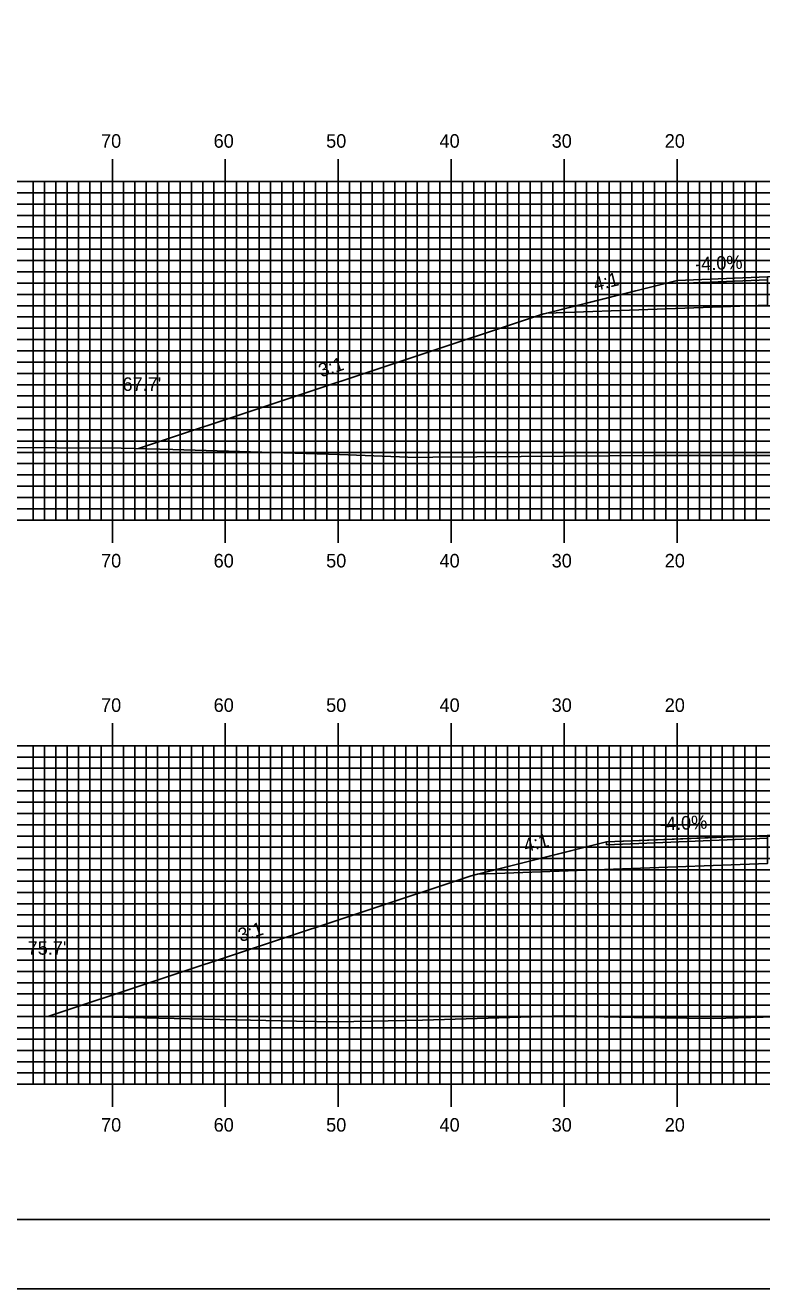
# Model space of a CAD drawing. Extents: x 1762578 to 1762921, y 442591 to 442811.
# Drawn here: x 1762666.1 to 1762731.3, y 442590.5 to 442702.5 of the extents above; entities that cross this region are included whole.
import ezdxf

# ---------------------------------------------------------------- set-up
doc = ezdxf.new("R2010")
doc.units = 0
for name, color, linetype in [('ANNOTATION', 7, 'Continuous'), ('BORDER', 7, 'Continuous'), ('D_Roadway_Centerline', 7, 'Continuous'), ('D_Roadway_Edge_Shoulder', 7, 'Continuous'), ('D_Roadway_SlopeLines', 7, 'Continuous'), ('D_Roadway_SubGrade', 7, 'Continuous'), ('D_Text_Standard', 7, 'Continuous'), ('H_V ANNOTATION', 7, 'Continuous'), ('MAJOR', 7, 'Continuous'), ('MINOR', 7, 'Continuous'), ('PLOT BOUNDARY', 7, 'Continuous'), ('S_Roadway_Centerline', 7, 'Continuous')]:
    doc.layers.add(name, color=color, linetype=linetype)

msp = doc.modelspace()

# ---------------------------------------------------------------- linework, layer by layer
at = {"layer": 'BORDER'}
msp.add_lwpolyline([(1762594.18, 442596.67), (1762914.18, 442596.67), (1762914.18, 442806.67), (1762594.18, 442806.67)], close=True, dxfattribs=at)
at = {"layer": 'D_Roadway_Centerline'}
for points in [[(1762676.09, 442665.01), (1762676.09, 442665.01), (1762711.78, 442676.9), (1762712, 442676.96), (1762712.25, 442677.02), (1762712.25, 442677.02), (1762716.68, 442678.13), (1762723.78, 442679.9), (1762723.78, 442679.9), (1762731.78, 442680.22), (1762739.05, 442680.48), (1762743.78, 442680.66), (1762743.78, 442680.66), (1762755.78, 442681.09), (1762763.78, 442680.77), (1762764.26, 442680.65), (1762773.95, 442678.22), (1762775.78, 442677.77), (1762805.93, 442667.72), (1762805.95, 442667.71)], [(1762668.07, 442614.67), (1762668.08, 442614.67), (1762705.54, 442627.15), (1762706.12, 442627.3), (1762706.12, 442627.3), (1762717.54, 442630.15), (1762717.54, 442630.15), (1762726.98, 442630.53), (1762731.78, 442630.72), (1762731.78, 442630.72), (1762738.78, 442630.98), (1762743.78, 442631.16), (1762743.78, 442631.16), (1762750.76, 442631.41), (1762755.78, 442631.59), (1762755.78, 442631.59), (1762763.78, 442631.27), (1762773.95, 442628.72), (1762773.95, 442628.72), (1762774.91, 442628.48), (1762775.78, 442628.27), (1762802.49, 442619.36), (1762811.53, 442616.35)]]:
    msp.add_lwpolyline(points, dxfattribs=at)
at = {"layer": 'D_Roadway_Edge_Shoulder'}
for points in [[(1762731.78, 442680.22), (1762723.78, 442679.9), (1762723.78, 442679.65), (1762731.78, 442679.97)], [(1762731.78, 442630.72), (1762717.54, 442630.15), (1762717.54, 442629.9), (1762731.78, 442630.47)]]:
    msp.add_lwpolyline(points, close=True, dxfattribs=at)
at = {"layer": 'D_Roadway_SlopeLines'}
for points in [[(1762723.78, 442679.9), (1762711.78, 442676.9), (1762676.09, 442665.01)], [(1762717.54, 442630.15), (1762705.54, 442627.15), (1762668.07, 442614.67)]]:
    msp.add_lwpolyline(points, dxfattribs=at)
at = {"layer": 'D_Roadway_SubGrade'}
for points in [[(1762723.78, 442679.65), (1762731.78, 442679.97), (1762731.78, 442679.56), (1762731.78, 442677.72), (1762712.25, 442677.02), (1762723.78, 442679.9)], [(1762717.54, 442629.9), (1762731.78, 442630.47), (1762731.78, 442630.06), (1762731.78, 442628.22), (1762706.12, 442627.3), (1762717.54, 442630.15)]]:
    msp.add_lwpolyline(points, close=True, dxfattribs=at)
at = {"layer": 'MAJOR'}
for p, q in [((1762673.78, 442690.67), (1762673.78, 442688.67)), ((1762683.78, 442690.67), (1762683.78, 442688.67)), ((1762693.78, 442690.67), (1762693.78, 442688.67)), ((1762703.78, 442690.67), (1762703.78, 442688.67)), ((1762713.78, 442690.67), (1762713.78, 442688.67)), ((1762723.78, 442690.67), (1762723.78, 442688.67)), ((1762603.78, 442688.67), (1762883.78, 442688.67)), ((1762603.78, 442688.67), (1762883.78, 442688.67)), ((1762673.78, 442658.67), (1762673.78, 442688.67)), ((1762683.78, 442658.67), (1762683.78, 442688.67)), ((1762693.78, 442658.67), (1762693.78, 442688.67)), ((1762703.78, 442658.67), (1762703.78, 442688.67)), ((1762713.78, 442658.67), (1762713.78, 442688.67)), ((1762723.78, 442658.67), (1762723.78, 442688.67)), ((1762603.78, 442683.67), (1762883.78, 442683.67)), ((1762603.78, 442678.67), (1762883.78, 442678.67)), ((1762603.78, 442673.67), (1762883.78, 442673.67)), ((1762603.78, 442668.67), (1762883.78, 442668.67)), ((1762603.78, 442663.67), (1762883.78, 442663.67)), ((1762603.78, 442658.67), (1762883.78, 442658.67)), ((1762603.78, 442658.67), (1762883.78, 442658.67)), ((1762673.78, 442656.66), (1762673.78, 442658.67)), ((1762683.78, 442656.66), (1762683.78, 442658.67)), ((1762693.78, 442656.66), (1762693.78, 442658.67)), ((1762703.78, 442656.66), (1762703.78, 442658.67)), ((1762713.78, 442656.66), (1762713.78, 442658.67)), ((1762723.78, 442656.66), (1762723.78, 442658.67)), ((1762673.78, 442640.67), (1762673.78, 442638.67)), ((1762683.78, 442640.67), (1762683.78, 442638.67)), ((1762693.78, 442640.67), (1762693.78, 442638.67)), ((1762703.78, 442640.67), (1762703.78, 442638.67)), ((1762713.78, 442640.67), (1762713.78, 442638.67)), ((1762723.78, 442640.67), (1762723.78, 442638.67)), ((1762603.78, 442638.67), (1762883.78, 442638.67)), ((1762603.78, 442638.67), (1762883.78, 442638.67)), ((1762673.78, 442608.67), (1762673.78, 442638.67)), ((1762683.78, 442608.67), (1762683.78, 442638.67)), ((1762693.78, 442608.67), (1762693.78, 442638.67)), ((1762703.78, 442608.67), (1762703.78, 442638.67)), ((1762713.78, 442608.67), (1762713.78, 442638.67)), ((1762723.78, 442608.67), (1762723.78, 442638.67)), ((1762603.78, 442633.67), (1762883.78, 442633.67)), ((1762603.78, 442628.67), (1762883.78, 442628.67)), ((1762603.78, 442623.67), (1762883.78, 442623.67)), ((1762603.78, 442618.67), (1762883.78, 442618.67)), ((1762603.78, 442613.67), (1762883.78, 442613.67)), ((1762603.78, 442608.67), (1762883.78, 442608.67)), ((1762603.78, 442608.67), (1762883.78, 442608.67)), ((1762673.78, 442606.66), (1762673.78, 442608.67)), ((1762683.78, 442606.66), (1762683.78, 442608.67)), ((1762693.78, 442606.66), (1762693.78, 442608.67)), ((1762703.78, 442606.66), (1762703.78, 442608.67)), ((1762713.78, 442606.66), (1762713.78, 442608.67)), ((1762723.78, 442606.66), (1762723.78, 442608.67))]:
    msp.add_line(p, q, dxfattribs=at)
at = {"layer": 'MINOR'}
for p, q in [((1762666.78, 442658.67), (1762666.78, 442688.67)), ((1762667.78, 442658.67), (1762667.78, 442688.67)), ((1762668.78, 442658.67), (1762668.78, 442688.67)), ((1762669.78, 442658.67), (1762669.78, 442688.67)), ((1762670.78, 442658.67), (1762670.78, 442688.67)), ((1762671.78, 442658.67), (1762671.78, 442688.67)), ((1762672.78, 442658.67), (1762672.78, 442688.67)), ((1762674.78, 442658.67), (1762674.78, 442688.67)), ((1762675.78, 442658.67), (1762675.78, 442688.67)), ((1762676.78, 442658.67), (1762676.78, 442688.67)), ((1762677.78, 442658.67), (1762677.78, 442688.67)), ((1762678.78, 442658.67), (1762678.78, 442688.67)), ((1762679.78, 442658.67), (1762679.78, 442688.67)), ((1762680.78, 442658.67), (1762680.78, 442688.67)), ((1762681.78, 442658.67), (1762681.78, 442688.67)), ((1762682.78, 442658.67), (1762682.78, 442688.67)), ((1762684.78, 442658.67), (1762684.78, 442688.67)), ((1762685.78, 442658.67), (1762685.78, 442688.67)), ((1762686.78, 442658.67), (1762686.78, 442688.67)), ((1762687.78, 442658.67), (1762687.78, 442688.67)), ((1762688.78, 442658.67), (1762688.78, 442688.67)), ((1762689.78, 442658.67), (1762689.78, 442688.67)), ((1762690.78, 442658.67), (1762690.78, 442688.67)), ((1762691.78, 442658.67), (1762691.78, 442688.67)), ((1762692.78, 442658.67), (1762692.78, 442688.67)), ((1762694.78, 442658.67), (1762694.78, 442688.67)), ((1762695.78, 442658.67), (1762695.78, 442688.67)), ((1762696.78, 442658.67), (1762696.78, 442688.67)), ((1762697.78, 442658.67), (1762697.78, 442688.67)), ((1762698.78, 442658.67), (1762698.78, 442688.67)), ((1762699.78, 442658.67), (1762699.78, 442688.67)), ((1762700.78, 442658.67), (1762700.78, 442688.67)), ((1762701.78, 442658.67), (1762701.78, 442688.67)), ((1762702.78, 442658.67), (1762702.78, 442688.67)), ((1762704.78, 442658.67), (1762704.78, 442688.67)), ((1762705.78, 442658.67), (1762705.78, 442688.67)), ((1762706.78, 442658.67), (1762706.78, 442688.67)), ((1762707.78, 442658.67), (1762707.78, 442688.67)), ((1762708.78, 442658.67), (1762708.78, 442688.67)), ((1762709.78, 442658.67), (1762709.78, 442688.67)), ((1762710.78, 442658.67), (1762710.78, 442688.67)), ((1762711.78, 442658.67), (1762711.78, 442688.67)), ((1762712.78, 442658.67), (1762712.78, 442688.67)), ((1762714.78, 442658.67), (1762714.78, 442688.67)), ((1762715.78, 442658.67), (1762715.78, 442688.67)), ((1762716.78, 442658.67), (1762716.78, 442688.67)), ((1762717.78, 442658.67), (1762717.78, 442688.67)), ((1762718.78, 442658.67), (1762718.78, 442688.67)), ((1762719.78, 442658.67), (1762719.78, 442688.67)), ((1762720.78, 442658.67), (1762720.78, 442688.67)), ((1762721.78, 442658.67), (1762721.78, 442688.67)), ((1762722.78, 442658.67), (1762722.78, 442688.67)), ((1762724.78, 442658.67), (1762724.78, 442688.67)), ((1762725.78, 442658.67), (1762725.78, 442688.67)), ((1762726.78, 442658.67), (1762726.78, 442688.67)), ((1762727.78, 442658.67), (1762727.78, 442688.67)), ((1762728.78, 442658.67), (1762728.78, 442688.67)), ((1762729.78, 442658.67), (1762729.78, 442688.67)), ((1762730.78, 442658.67), (1762730.78, 442688.67)), ((1762603.78, 442687.67), (1762883.78, 442687.67)), ((1762603.78, 442686.67), (1762883.78, 442686.67)), ((1762603.78, 442685.67), (1762883.78, 442685.67)), ((1762603.78, 442684.67), (1762883.78, 442684.67)), ((1762603.78, 442682.67), (1762883.78, 442682.67)), ((1762603.78, 442681.67), (1762883.78, 442681.67)), ((1762603.78, 442680.67), (1762883.78, 442680.67)), ((1762603.78, 442679.67), (1762883.78, 442679.67)), ((1762603.78, 442677.67), (1762883.78, 442677.67)), ((1762603.78, 442676.67), (1762883.78, 442676.67)), ((1762603.78, 442675.67), (1762883.78, 442675.67)), ((1762603.78, 442674.67), (1762883.78, 442674.67)), ((1762603.78, 442672.67), (1762883.78, 442672.67)), ((1762603.78, 442671.67), (1762883.78, 442671.67)), ((1762603.78, 442670.67), (1762883.78, 442670.67)), ((1762603.78, 442669.67), (1762883.78, 442669.67)), ((1762603.78, 442667.67), (1762883.78, 442667.67)), ((1762603.78, 442666.67), (1762883.78, 442666.67)), ((1762603.78, 442665.67), (1762883.78, 442665.67)), ((1762603.78, 442664.67), (1762883.78, 442664.67)), ((1762603.78, 442662.67), (1762883.78, 442662.67)), ((1762603.78, 442661.67), (1762883.78, 442661.67)), ((1762603.78, 442660.67), (1762883.78, 442660.67)), ((1762603.78, 442659.67), (1762883.78, 442659.67)), ((1762666.78, 442608.67), (1762666.78, 442638.67)), ((1762667.78, 442608.67), (1762667.78, 442638.67)), ((1762668.78, 442608.67), (1762668.78, 442638.67)), ((1762669.78, 442608.67), (1762669.78, 442638.67)), ((1762670.78, 442608.67), (1762670.78, 442638.67)), ((1762671.78, 442608.67), (1762671.78, 442638.67)), ((1762672.78, 442608.67), (1762672.78, 442638.67)), ((1762674.78, 442608.67), (1762674.78, 442638.67)), ((1762675.78, 442608.67), (1762675.78, 442638.67)), ((1762676.78, 442608.67), (1762676.78, 442638.67)), ((1762677.78, 442608.67), (1762677.78, 442638.67)), ((1762678.78, 442608.67), (1762678.78, 442638.67)), ((1762679.78, 442608.67), (1762679.78, 442638.67)), ((1762680.78, 442608.67), (1762680.78, 442638.67)), ((1762681.78, 442608.67), (1762681.78, 442638.67)), ((1762682.78, 442608.67), (1762682.78, 442638.67)), ((1762684.78, 442608.67), (1762684.78, 442638.67)), ((1762685.78, 442608.67), (1762685.78, 442638.67)), ((1762686.78, 442608.67), (1762686.78, 442638.67)), ((1762687.78, 442608.67), (1762687.78, 442638.67)), ((1762688.78, 442608.67), (1762688.78, 442638.67)), ((1762689.78, 442608.67), (1762689.78, 442638.67)), ((1762690.78, 442608.67), (1762690.78, 442638.67)), ((1762691.78, 442608.67), (1762691.78, 442638.67)), ((1762692.78, 442608.67), (1762692.78, 442638.67)), ((1762694.78, 442608.67), (1762694.78, 442638.67)), ((1762695.78, 442608.67), (1762695.78, 442638.67)), ((1762696.78, 442608.67), (1762696.78, 442638.67)), ((1762697.78, 442608.67), (1762697.78, 442638.67)), ((1762698.78, 442608.67), (1762698.78, 442638.67)), ((1762699.78, 442608.67), (1762699.78, 442638.67)), ((1762700.78, 442608.67), (1762700.78, 442638.67)), ((1762701.78, 442608.67), (1762701.78, 442638.67)), ((1762702.78, 442608.67), (1762702.78, 442638.67)), ((1762704.78, 442608.67), (1762704.78, 442638.67)), ((1762705.78, 442608.67), (1762705.78, 442638.67)), ((1762706.78, 442608.67), (1762706.78, 442638.67)), ((1762707.78, 442608.67), (1762707.78, 442638.67)), ((1762708.78, 442608.67), (1762708.78, 442638.67)), ((1762709.78, 442608.67), (1762709.78, 442638.67)), ((1762710.78, 442608.67), (1762710.78, 442638.67)), ((1762711.78, 442608.67), (1762711.78, 442638.67)), ((1762712.78, 442608.67), (1762712.78, 442638.67)), ((1762714.78, 442608.67), (1762714.78, 442638.67)), ((1762715.78, 442608.67), (1762715.78, 442638.67)), ((1762716.78, 442608.67), (1762716.78, 442638.67)), ((1762717.78, 442608.67), (1762717.78, 442638.67)), ((1762718.78, 442608.67), (1762718.78, 442638.67)), ((1762719.78, 442608.67), (1762719.78, 442638.67)), ((1762720.78, 442608.67), (1762720.78, 442638.67)), ((1762721.78, 442608.67), (1762721.78, 442638.67)), ((1762722.78, 442608.67), (1762722.78, 442638.67)), ((1762724.78, 442608.67), (1762724.78, 442638.67)), ((1762725.78, 442608.67), (1762725.78, 442638.67)), ((1762726.78, 442608.67), (1762726.78, 442638.67)), ((1762727.78, 442608.67), (1762727.78, 442638.67)), ((1762728.78, 442608.67), (1762728.78, 442638.67)), ((1762729.78, 442608.67), (1762729.78, 442638.67)), ((1762730.78, 442608.67), (1762730.78, 442638.67)), ((1762603.78, 442637.67), (1762883.78, 442637.67)), ((1762603.78, 442636.67), (1762883.78, 442636.67)), ((1762603.78, 442635.67), (1762883.78, 442635.67)), ((1762603.78, 442634.67), (1762883.78, 442634.67)), ((1762603.78, 442632.67), (1762883.78, 442632.67)), ((1762603.78, 442631.67), (1762883.78, 442631.67)), ((1762603.78, 442630.67), (1762883.78, 442630.67)), ((1762603.78, 442629.67), (1762883.78, 442629.67)), ((1762603.78, 442627.67), (1762883.78, 442627.67)), ((1762603.78, 442626.67), (1762883.78, 442626.67)), ((1762603.78, 442625.67), (1762883.78, 442625.67)), ((1762603.78, 442624.67), (1762883.78, 442624.67)), ((1762603.78, 442622.67), (1762883.78, 442622.67)), ((1762603.78, 442621.67), (1762883.78, 442621.67)), ((1762603.78, 442620.67), (1762883.78, 442620.67)), ((1762603.78, 442619.67), (1762883.78, 442619.67)), ((1762603.78, 442617.67), (1762883.78, 442617.67)), ((1762603.78, 442616.67), (1762883.78, 442616.67)), ((1762603.78, 442615.67), (1762883.78, 442615.67)), ((1762603.78, 442614.67), (1762883.78, 442614.67)), ((1762603.78, 442612.67), (1762883.78, 442612.67)), ((1762603.78, 442611.67), (1762883.78, 442611.67)), ((1762603.78, 442610.67), (1762883.78, 442610.67)), ((1762603.78, 442609.67), (1762883.78, 442609.67))]:
    msp.add_line(p, q, dxfattribs=at)
at = {"layer": 'PLOT BOUNDARY'}
msp.add_lwpolyline([(1762577.99, 442590.55), (1762917.99, 442590.55), (1762917.99, 442810.55), (1762577.99, 442810.55)], close=True, dxfattribs=at)
at = {"layer": 'S_Roadway_Centerline'}
for points in [[(1762663.21, 442665.11), (1762674.57, 442665.04), (1762679.13, 442664.93), (1762693.88, 442664.49), (1762700.7, 442664.23), (1762702.15, 442664.25), (1762721.7, 442664.39), (1762737.26, 442664.39), (1762738.93, 442664.41), (1762740.1, 442664.43), (1762744.54, 442664.53), (1762758.8, 442665.01), (1762768.12, 442665.12), (1762773.73, 442665.16), (1762777.32, 442665.4), (1762785.99, 442666.35), (1762797.39, 442667.15), (1762798.62, 442667.21), (1762800.16, 442667.29), (1762816.36, 442668.47)], [(1762657.2, 442614.76), (1762673.81, 442614.61), (1762690.09, 442614.26), (1762693.66, 442614.2), (1762701.23, 442614.34), (1762713.81, 442614.72), (1762716.03, 442614.67), (1762719.97, 442614.59), (1762727.01, 442614.49), (1762731.42, 442614.61), (1762739.16, 442614.78), (1762750.36, 442615.08), (1762751.9, 442615.09), (1762762.68, 442614.98), (1762770.55, 442615.05), (1762780.92, 442615.43), (1762790.62, 442615.71), (1762798.83, 442615.96), (1762809.91, 442616.24)]]:
    msp.add_lwpolyline(points, dxfattribs=at)

# ---------------------------------------------------------------- texts
at = {"layer": 'ANNOTATION'}
for s, rotation, p in [('-4.0%', 2.2906, (1762725.41, 442680.77)), ('4:1', 14.0405, (1762716.55, 442678.96)), ('3:1', 18.4354, (1762692.27, 442671.31)), ('-4.0%', 2.2918, (1762722.29, 442631.15)), ('4:1', 14.0362, (1762710.37, 442629.22)), ('3:1', 18.4355, (1762685.15, 442621.26))]:
    msp.add_text(s, height=1.2, rotation=rotation, dxfattribs=at).set_placement(p)
at = {"layer": 'D_Text_Standard'}
for s, p in [("67.7'", (1762674.68, 442670.12)), ("75.7'", (1762666.28, 442620.15))]:
    msp.add_text(s, height=1.2, dxfattribs=at).set_placement(p)
at = {"layer": 'H_V ANNOTATION'}
for s, p in [('70', (1762672.78, 442691.67)), ('60', (1762682.75, 442691.67)), ('50', (1762692.71, 442691.67)), ('40', (1762702.75, 442691.67)), ('30', (1762712.68, 442691.67)), ('20', (1762722.69, 442691.67)), ('70', (1762672.78, 442654.47)), ('60', (1762682.75, 442654.47)), ('50', (1762692.71, 442654.47)), ('40', (1762702.75, 442654.47)), ('30', (1762712.68, 442654.47)), ('20', (1762722.69, 442654.47)), ('70', (1762672.78, 442641.67)), ('60', (1762682.75, 442641.67)), ('50', (1762692.71, 442641.67)), ('40', (1762702.75, 442641.67)), ('30', (1762712.68, 442641.67)), ('20', (1762722.69, 442641.67)), ('70', (1762672.78, 442604.47)), ('60', (1762682.75, 442604.47)), ('50', (1762692.71, 442604.47)), ('40', (1762702.75, 442604.47)), ('30', (1762712.68, 442604.47)), ('20', (1762722.69, 442604.47))]:
    msp.add_text(s, height=1.2, dxfattribs=at).set_placement(p)

doc.saveas('drawing.dxf')
